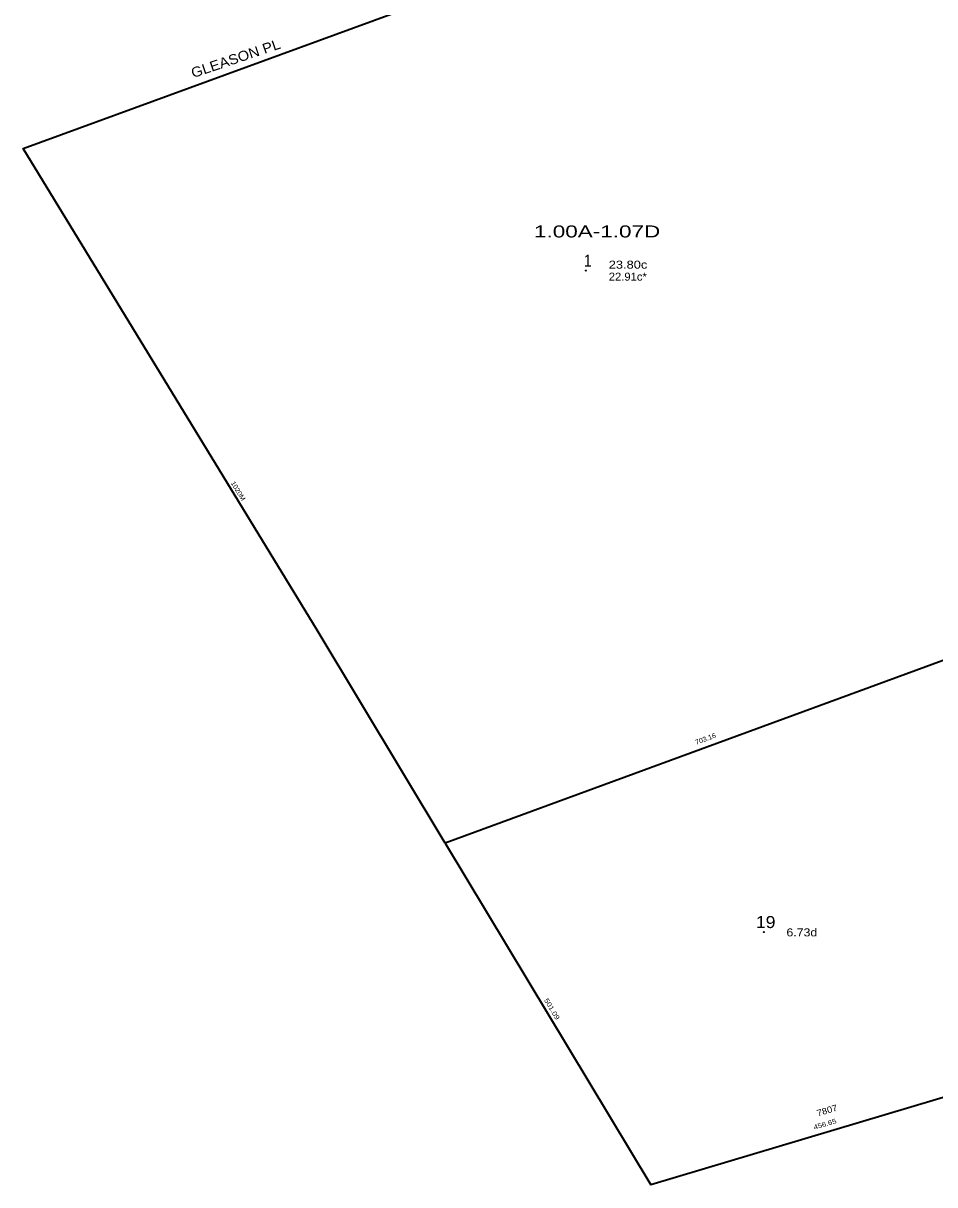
# Model space of a CAD drawing. Extents: x 2546959 to 2550387, y 581906 to 585027.
# Drawn here: x 2546959 to 2548097, y 581906 to 583358 of the extents above; entities that cross this region are included whole.
import ezdxf
from ezdxf.enums import TextEntityAlignment as Align

# ---------------------------------------------------------------- set-up
doc = ezdxf.new("R2010")
doc.units = 0
doc.header["$LTSCALE"] = 2.4
doc.header["$PDMODE"] = 32
doc.header["$PDSIZE"] = 1.2
for name, color, linetype in [('20', 7, 'Continuous'), ('38', 7, 'Continuous'), ('39', 7, 'Continuous'), ('41', 7, 'Continuous'), ('42', 7, 'Continuous')]:
    doc.layers.add(name, color=color, linetype=linetype)
doc.layers.add('40', color=7, linetype='Continuous', lineweight=35)

msp = doc.modelspace()

# ---------------------------------------------------------------- linework, layer by layer
at = {"layer": '40'}
for p, q in [((2547485.72, 582333.191), (2547325.615, 582599.385)), ((2548140.45, 582573.76), (2547485.72, 582333.191)), ((2547485.72, 582333.191), (2547742.428, 581906.383)), ((2548181.098, 582037.405), (2547742.428, 581906.383))]:
    msp.add_line(p, q, dxfattribs=at)
msp.add_lwpolyline([(2547325.615, 582599.385), (2546958.539, 583201.411), (2547418.933, 583369.569)], dxfattribs=at)
at = {"layer": '41'}
for p in [(2547661.287, 583048.828), (2547883.396, 582222.181)]:
    msp.add_point(p, dxfattribs=at)

# ---------------------------------------------------------------- texts
at = {"layer": '20', "width": 1.1}
msp.add_text('GLEASON PL', height=12.5, rotation=18.729, dxfattribs=at).set_placement((2547225.91, 583308.06), align=Align.CENTER)
at = {"layer": '38'}
for s, width, p in [('1.00A-1.07D', 1.4, (2547675.345, 583090.245)), ('1', 0.9, (2547663.767, 583053.828)), ('19', 1.1, (2547885.876, 582227.181))]:
    msp.add_text(s, height=15, dxfattribs=dict(at, width=width)).set_placement(p, align=Align.CENTER)
at = {"layer": '39', "width": 1.1}
msp.add_text('7807', height=8, rotation=16.63, dxfattribs=at).set_placement((2547963.72, 581995.478), align=Align.CENTER)
at = {"layer": '42'}
for s, width, p in [('23.80c', 1.2, (2547689.851, 583051.257)), ('22.91c*', 1.05, (2547689.851, 583036.257)), ('6.73d', 1.15, (2547911.845, 582216.766))]:
    msp.add_text(s, height=10, dxfattribs=dict(at, width=width)).set_placement(p)
for s, rotation, width, p in [('1020M', 301.266, 1.1, (2547224.487, 582771.885)), ('703.16', 20.175, 1.1, (2547811.74, 582460.862)), ('501.09', 301.025, 1.2, (2547616.404, 582124.447)), ('456.65', 16.63, 1.2, (2547960.805, 581979.321))]:
    msp.add_text(s, height=5.999, rotation=rotation, dxfattribs=dict(at, width=width)).set_placement(p, align=Align.CENTER)

doc.saveas('drawing.dxf')
